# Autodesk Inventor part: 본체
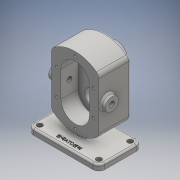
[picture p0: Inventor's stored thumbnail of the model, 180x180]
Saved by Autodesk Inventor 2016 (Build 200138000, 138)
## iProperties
Created: 2019-03
Part Number: 본체
Material: 일반
Document SubType Name: Modeling
Designer: USER
Density: 1 g/cm^3
Appearance: 기본값
Author: USER
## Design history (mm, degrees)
sketch "스케치1"
  geometry: L1 (0, 0)-(120, 0); L2 (120, 0)-(120, 73); L3 (120, 73)-(0, 73); L4 (0, 73)-(0, 0); 1 further point
  constraints: 8 end point, 2 perpendicular, 1 coincident, 1 horizontal
  dimensions: "d3" = 120 distance of L1.start L1.end; "d4" = 73 distance of L1.end L2.end; "d5" = 120 distance of L2.end L3.end
extrude "돌출1" new body sketch "스케치1" distance "d6" = 10; taper "d7" = 0 deg
fillet "모깎기1" dims "d8" = 10
sketch "스케치2"
  geometry: L1 (110, 73)-(10, 73) reference; L2 (0, 63)-(0, 10) reference; L3 (10, 0)-(110, 0) reference; L4 (120, 10)-(120, 63) reference; L5 (110, 73)-(10, 73) reference; C1 r 4.5 at (10, 63); C2 r 4.5 at (10, 10); C3 r 4.5 at (110, 63); C4 r 4.5 at (110, 10); A1 r 10 centre (10, 63) between (10, 73) and (0, 63) reference; A2 r 10 centre (10, 10) between (0, 10) and (10, 0) reference; A3 r 10 centre (110, 10) between (110, 0) and (120, 10) reference; A4 r 10 centre (110, 63) between (120, 63) and (110, 73) reference; 1 further point
  constraints: 4 centre point, 4 coincident
  dimensions: "d9" = 9 diameter of C1; "d10" = 9 diameter of C2; "d11" = 9 diameter of C3; "d12" = 9 diameter of C4
extrude "돌출2" cut sketch "스케치2" distance "d13" = 10; taper "d14" = 0 deg
node "작업 평면2"
sketch "스케치4"
  geometry: L1 (-10, 0)-(-110, 0) reference; L2 (-60, 0)-(-60, 78); L3 (-20, 33.279)-(-20, 122.721); L4 (-100, 33.279)-(-100, 122.721); A1 r 60 centre (-60, 78) between (-100, 33.279) and (-20, 33.279); A2 r 60 centre (-60, 78) between (-20, 122.721) and (-100, 122.721); 1 further point
  constraints: 6 end point, 4 point on circle, 2 centre point, 2 parallel, 1 coincident, 1 midpoint, 1 vertical
  dimensions: "d23" = 78 distance of L2.start L2.end; "d24" = 40 distance between parallel lines of L2 L3; "d25" = 40 distance between parallel lines of L2 L4; "d27" = 60 radius of A2; "d28" = 60 radius of A1
extrude "돌출3" join sketch "스케치4" distance "d29" = 53; taper "d30" = 0 deg
sketch "스케치5"
  geometry: L1 (20, 122.721)-(20, 33.279) reference; L2 (100, 33.279)-(100, 122.721) reference; L3 (20, 122.721)-(20, 33.279) reference; L4 (36, 78)-(84, 78); L5 (100, 33.279)-(100, 122.721) reference; L6 (60, 124)-(60, 32); L7 (36, 100)-(36, 56); L8 (84, 100)-(84, 56); A1 r 60 centre (60, 78) between (20, 33.279) and (100, 33.279) reference; A2 r 60 centre (60, 78) between (100, 122.721) and (20, 122.721) reference; A3 r 60 centre (60, 78) between (20, 33.279) and (100, 33.279) reference; A4 r 24 centre (60, 100) between (84, 100) and (36, 100); A5 r 24 centre (60, 56) between (36, 56) and (84, 56); 5 further points
  constraints: 8 end point, 7 midpoint, 7 point on circle, 3 horizontal alignment, 2 centre point, 2 point on line, 2 vertical alignment
  dimensions: "d36" = 24 radius of A5; "d37" = 44 distance of L7.start L7.end; "d38" = 44 distance of L8.start L8.end; "d39" = 16 distance between parallel lines of L1 L7; "d40" = 48 distance of L4.start L4.end; "d41" = 24 radius of A4
extrude "돌출4" cut sketch "스케치5" distance "d42" = 29; taper "d43" = 0 deg
sketch "스케치6"
  geometry: L1 (84, 100)-(84, 56) reference; L2 (36, 56)-(36, 100) reference; C1 r 12.5 at (60, 100); C2 r 12.5 at (60, 56); A1 r 24 centre (60, 100) between (84, 100) and (36, 100) reference; A2 r 24 centre (60, 56) between (36, 56) and (84, 56) reference; 1 further point
  constraints: 2 centre point, 2 coincident
  dimensions: "d44" = 25 diameter of C1; "d45" = 25 diameter of C2
extrude "돌출5" cut sketch "스케치6" distance "d46" = 15; taper "d47" = 0 deg
sketch "스케치8"
  geometry: L1 (20, -33.279)-(20, -122.721) reference; L2 (100, -122.721)-(100, -33.279) reference; L3 (60, -78)-(60, -100); C1 r 19 at (60, -100); A1 r 60 centre (60, -78) between (20, -122.721) and (100, -122.721) reference; A2 r 60 centre (60, -78) between (100, -33.279) and (20, -33.279) reference; 1 further point
  constraints: 2 end point, 1 centre point, 1 coincident, 1 vertical
  dimensions: "d48" = 22 distance of L3.start L3.end; "d49" = 38 diameter of C1
extrude "돌출6" join sketch "스케치8" distance "d50" = 17; taper "d51" = 0 deg
node "작업 평면3"
sketch "스케치10"
  geometry: L1 (64, 87.5)-(64, 112.5) reference; L2 (64, 100)-(90, 100); L3 (20, 100)-(49, 100) reference; L4 (64, 100)-(64, 108.5); L5 (90, 81)-(90, 119) reference; L6 (90, 100)-(90, 114); L7 (90, 114)-(82.7, 114); L8 (82.7, 114)-(82.7, 108.5); L9 (82.7, 108.5)-(64, 108.5); 1 further point
  constraints: 12 end point, 3 perpendicular, 2 midpoint, 2 point on line, 1 collinear
  dimensions: "d54" = 14 distance of L2.end L6.end; "d55" = 7.3 distance of L6.end L7.end; "d56" = 17 diameter of L9 L2
revolve "회전1" sketch "스케치10" stored, may be unused: angle "d57" = 90 deg
sketch "스케치11"
  geometry: L1 (10, 0)-(110, 0) reference; L2 (60, 0)-(60, 73); L3 (110, 73)-(10, 73) reference; L4 (54, 30)-(54, 73); L5 (66, 30)-(66, 73); L6 (54, 73)-(66, 73); L7 (66, 30)-(54, 30); 1 further point
  constraints: 10 end point, 3 parallel, 2 midpoint, 1 collinear
  dimensions: "d58" = 6 distance between parallel lines of L2 L4; "d59" = 6 distance between parallel lines of L2 L5; "d60" = 43 distance between parallel lines of L3 L7; "d62" = 43 distance of L5.start L5.end
extrude "돌출7" join sketch "스케치11" distance "d63" = 15; taper "d64" = 0 deg
sketch "스케치12"
  geometry: L1 (84, 100)-(84, 56) reference; L2 (36, 56)-(36, 100) reference; L3 (20, 122.721)-(20, 33.279) reference; L4 (100, 33.279)-(100, 122.721) reference; L5 (29, 100)-(29, 56); L6 (91, 100)-(91, 56); A1 r 24 centre (60, 100) between (84, 100) and (36, 100) reference; A2 r 24 centre (60, 56) between (36, 56) and (84, 56) reference; A3 r 60 centre (60, 78) between (20, 33.279) and (100, 33.279) reference; A4 r 60 centre (60, 78) between (100, 122.721) and (20, 122.721) reference; A5 r 31 centre (60, 56) between (29, 56) and (91, 56); A6 r 31 centre (60, 100) between (60, 131) and (29, 100); 6 further points
  constraints: 6 coincident, 6 point on circle, 4 end point, 4 tangent, 2 centre point, 2 vertical alignment
  dimensions: "d65" = 62 diameter of A5; "d66" = 62 diameter of A6
hole "구멍1" sketch "스케치12" at (60, 131), (29, 100), (91, 100), (91, 56), (29, 56), (60, 25) diameter "d67" = 4.134; stored, may be unused: countersink angle "d71" = 90 deg, drill point angle "d73" = 118 deg; dims "d68" = 10, "d69" = 4, "d70" = 2, "d72" = 12
sketch "스케치13"
  geometry: L1 (122.721, -10)-(122.721, -63) reference; L2 (89.443, -53)-(0, -53) reference; C1 r 11 at (44.721, -39); 1 further point
  constraints: 1 centre point
  dimensions: "d117" = 14 distance from line of L2 C1.centre; "d118" = 78 distance from line of L1 C1.centre; "d119" = 22 diameter of C1
extrude "돌출8" join sketch "스케치13" distance "d77" = 8; taper "d78" = 0 deg
sketch "스케치14"
  geometry: L1 (-33.279, -10)-(-33.279, -63) reference; L2 (89.443, -53)-(0, -53) reference; C1 r 11 at (44.721, -39); 1 further point
  constraints: 1 centre point
  dimensions: "d80" = 22 diameter of C1; "d120" = 14 distance from line of C1.centre L2; "d121" = 78 distance from line of L1 C1.centre
extrude "돌출9" join sketch "스케치14" distance "d81" = 8; taper "d82" = 0 deg
sketch "스케치15"
  geometry: C1 r 11 at (0, 0) reference; 2 further points
  constraints: 1 coincident
  node "투영된 루프8"
sketch "스케치16"
  geometry: C1 r 11 at (0, 0) reference; 2 further points
  constraints: 1 coincident
hole "구멍2" sketch "스케치16" at (0, 0) diameter "d83" = 8.376; stored, may be unused: countersink angle "d87" = 90 deg, drill point angle "d89" = 118 deg; dims "d84" = 29, "d85" = 4, "d86" = 2, "d88" = 30
hole "구멍3" sketch "스케치15" diameter "d90" = 8.376; stored, may be unused: countersink angle "d94" = 90 deg, drill point angle "d96" = 118 deg; dims "d91" = 29, "d92" = 4, "d93" = 2, "d95" = 30
node "작업 평면4"
sketch "스케치17"
  geometry: L1 (0, 63)-(0, 10) reference; L2 (10, 0)-(110, 0) reference; 2 further points
  constraints: 1 other
  dimensions: "d98" = 60 distance from line of L1 point (60, 10); "d99" = 10 distance from line of L2 point (60, 10)
feature "엠보싱1" sketch "스케치17" dims "d3" = 120, "d100" = 0.5, "d101" = 0
fillet "모깎기3" dims "d103" = 10
fillet "모깎기5" dims "d105" = 3
chamfer "모따기1" distance "d108" = 1; stored, may be unused: second distance "d109" = 2, angle "d110" = 45 deg
fillet "모깎기8" dims "d111" = 3
chamfer "모따기2" distance "d112" = 0.7; stored, may be unused: second distance "d113" = 2, angle "d114" = 30 deg
fillet "모깎기9" dims "d115" = 0.5
fillet "모깎기10" dims "d116" = 3
fillet "모깎기11" dims "d122" = 3
fillet "모깎기12" dims "d123" = 3
fillet "모깎기13" dims "d124" = 3
node "솔리드1"
node "투영된 루프1"
node "투영된 루프2"
node "투영된 루프3"
node "투영된 루프5"
node "투영된 루프7"
node "투영된 루프9"
other parameters: "d22" = 73, "d33" = 48, "d34" = 48
